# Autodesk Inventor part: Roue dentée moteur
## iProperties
Author: Flavien MARTY
Shininess: 20.0
PropertySet Name: _Private Model Information
Created: 2001-10
Part Number: Roue dentée moteur
Material: Par défaut
Document SubType Name: Modélisation
Designer: Flavien MARTY
Control State: 0
Master: False
Checked Out: False
PropertySet Name: Design Tracking Control
Density: 0.0
Volumn: 0.0
Area: 0.0
PropertySet Name: Model Information
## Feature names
1. Base1
